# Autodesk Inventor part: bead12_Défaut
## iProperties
Shininess: 64.0
Length Units: 11269
Angle Units: 11279
Time Units: 11290
Mass Units: 11283
Length Display Precision: 3
Angle Display Precision: 2
Compacted: True
Part Number: bead12_Défaut
Document SubType Name: Modeling
Created: 2006-01
Material: Par défaut
Designer: Fricot
Density: 0.0
Volumn: 0.0
Area: 0.0
PropertySet Name: Model Information
Control State: 0
Master: False
Checked Out: False
Author: Fricot
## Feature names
1. Base1
